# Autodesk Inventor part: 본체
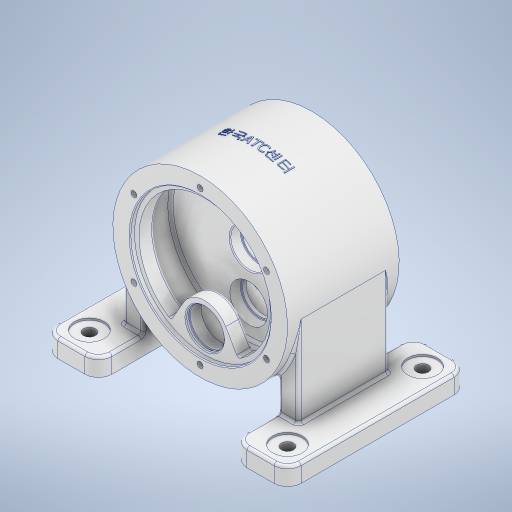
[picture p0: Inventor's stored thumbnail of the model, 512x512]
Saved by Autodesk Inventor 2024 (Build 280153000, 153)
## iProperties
Created: 2025-12
Part Number: 본체
Material: 알루미늄 6061
Document SubType Name: Modeling
Designer: Eud07
Density: 2.7 g/cm^3
Appearance: 알루미늄 - 평지
Mass: 5626.86 g
Surface Area: 3057.42 cm^2
Volume: 2084.02 cm^3
Author: Eud07
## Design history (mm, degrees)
sketch "스케치1"
  geometry: L1 (-97, -62)-(97, -62); L2 (97, -62)-(97, 62); L3 (97, 62)-(-97, 62); L4 (-97, 62)-(-97, -62); L5 (-97, -62)-(97, 62); L6 (97, -62)-(-97, 62); L7 (0, 62)-(0, -62); L8 (78, 62)-(78, 57); L9 (78, 57)-(73, 57); L10 (73, 57)-(73, 40); L11 (73, 40)-(87, 40); L12 (87, 40)-(87, 8); L13 (87, 8)-(0, 8); L14 (97, 0)-(0, 0); L15 (78, -62)-(78, -57); L16 (78, -57)-(73, -57); L17 (73, -57)-(73, -40); L18 (73, -40)-(87, -40); L19 (87, -40)-(87, -8); L20 (87, -8)-(0, -8); 2 further points
  constraints: 40 end point, 7 symmetric about line, 6 perpendicular, 5 midpoint, 2 horizontal, 2 parallel, 2 point on line, 1 vertical
  dimensions: "d0" = 124 distance of L1.end L2.end; "d1" = 97 distance between parallel lines of L7 L2; "d2" = 22 distance between parallel lines of L11 L3; "d3" = 5 distance of L8.start L8.end; "d4" = 32 distance of L11.end L12.end; "d5" = 78 distance between parallel lines of L7 L8; "d6" = 73 distance between parallel lines of L7 L10; "d7" = 87 distance between parallel lines of L7 L12
revolve "회전1" sketch "스케치1" stored, may be unused: angle "d8" = 90 deg
feature "면 삭제1"
sketch "스케치2" dims "d10" = 54
  geometry: L1 (-23.383, -39)-(-61.06, -104.259); L2 (0, 0)-(0, -116.93); L3 (23.383, -39)-(61.06, -104.259); C1 r 73 at (0, 0); 5 further points
  constraints: 6 end point, 2 symmetric about line, 1 centre point, 1 coincident, 1 vertical, 1 vertical alignment, 4 other
  dimensions: "d9" = 146 diameter of C1; "d11" = 52.5 distance of point (0, -52.5) point (0, 0); "d12" = 30 deg angle of L2 L1
extrude "돌출1" cut sketch "스케치2" distance "d13" = 17; taper "d14" = 0 deg
sketch "스케치3"
  geometry: C1 r 21 at (0, 0); C2 r 21 at (0, -52.5); C3 r 19 at (0, 0); C4 r 19 at (0, -52.5); A1 r 27 centre (0, -52.5) between (23.383, -39) and (-23.383, -39) reference; 1 further point
  constraints: 4 centre point, 3 coincident, 1 concentric
  dimensions: "d15" = 42 diameter of C1; "d16" = 42 diameter of C2; "d17" = 38 diameter of C3; "d18" = 38 diameter of C4
extrude "돌출2" cut sketch "스케치3" distance "d19" = 66; taper "d20" = 0 deg
extrude "돌출3" cut sketch "스케치3" extent not by distance; stored distance "d21" = 0; taper "d22" = 0 deg
sketch "스케치4"
  geometry: L1 (-52.5, 76.931)-(-52.5, 27.612); L2 (-87, 8)-(87, 8) reference; L3 (-73.5, 57)-(-31.5, 57) reference; L4 (-31.5, 57)-(-31.5, 40) reference; L5 (-31.5, 53.95)-(-30.25, 53.95); L6 (-30.25, 53.95)-(-30.25, 52); L7 (-30.25, 52)-(-31.5, 52); L8 (-31.5, 52)-(-31.5, 53.95); L9 (-39, 40)-(-25.5, 40) reference; 2 further points
  constraints: 10 end point, 2 parallel, 2 perpendicular, 1 horizontal, 1 point on line
  dimensions: "d23" = 21 distance from line of L3.end L1; "d24" = 1.95 distance of L5.end L6.end; "d25" = 12 distance between parallel lines of L9 L7; "d26" = 22.25 distance between parallel lines of L1 L6
revolve "회전2" sketch "스케치4" stored, may be unused: angle "d27" = 90 deg
node "작업 평면1"
sketch "스케치6"
  geometry: L1 (135, -100)-(75, -100); L2 (75, -100)-(75, 100); L3 (75, 100)-(135, 100); L4 (135, 100)-(135, -100); L5 (135, -100)-(75, 100); L6 (75, -100)-(135, 100); L7 (75, -50)-(97, -50); L8 (97, -50)-(97, 50); L9 (97, 50)-(75, 50); L10 (75, 50)-(75, -50); 3 further points
  constraints: 20 end point, 4 parallel, 2 horizontal, 2 midpoint, 2 perpendicular, 1 horizontal alignment, 1 point on line
  dimensions: "d29" = 60 distance of L2.end L3.end; "d30" = 75 distance from line of point (0, 0) L2; "d31" = 200 distance of L3.end L1.start; "d32" = 22 distance of L8.end L9.end; "d33" = 100 distance of L7.end L8.end; "d34" = 50 distance from line of point (0, 0) L7
extrude "돌출4" join sketch "스케치6" distance "d35" = 20; taper "d36" = 0 deg
extrude "돌출5" join sketch "스케치6" stored distance "d37" = 20; taper "d38" = 0 deg
fillet "모깎기1" dims "d39" = 15
sketch "스케치7"
  geometry: L1 (-135, 85)-(-135, -85) reference; L2 (73, -57)-(-73, -57) reference; 6 further points
  constraints: 2 midpoint
  dimensions: "d40" = 75 vertical distance of point (-135, 0) point (-110, 75); "d41" = 110 horizontal distance of point (0, -57) point (-110, 75)
hole "구멍1" sketch "스케치7" at (-110, 75) diameter "d42" = 13.5; stored, may be unused: countersink angle "d46" = 90 deg, drill point angle "d48" = 118 deg; dims "d43" = 6, "d44" = 33, "d45" = 2, "d47" = 8
sketch "스케치8"
  geometry: L1 (-75, -120)-(-75, -100) reference; L2 (-75, -112)-(-36.6, -89.83); L3 (-75, -100)-(-75, -61.514) reference; L4 (-75, -120)-(-90, -120) reference; A1 r 97 centre (0, 0) between (-36.6, -89.83) and (-75, -61.514) reference; 2 further points
  constraints: 2 end point, 1 coincident, 1 point on circle, 1 point on line
  dimensions: "d49" = 60 deg angle of L2 L3; "d50" = 8 distance from line of L4 point (-75, -112)
feature "리브1" sketch "스케치8" dims "d51" = 1, "d52" = 12, "d53" = 0, "d54" = 0, "d55" = 1, "d56" = 1
sketch "스케치9"
  geometry: 2 further points
  constraints: 1 vertical alignment
  dimensions: "d57" = 85 distance of point (0, 0) point (0, 85)
hole "구멍2" sketch "스케치9" at (0, 85) diameter "d58" = 6.647; stored, may be unused: countersink angle "d62" = 90 deg, drill point angle "d64" = 118 deg; dims "d59" = 16, "d60" = 33, "d61" = 2, "d63" = 18
node "작업 평면2"
sketch "스케치10"
  geometry: 2 further points
  constraints: 1 coincident, 1 other
feature "엠보싱1" sketch "스케치10" dims "d69" = 0.5, "d70" = 0
fillet "모깎기2" dims "d71" = 0.6
fillet "모깎기3" dims "d72" = 3
fillet "모깎기4" dims "d73" = 3
fillet "모깎기5" dims "d74" = 3
chamfer "모따기1" distance "d75" = 1; stored, may be unused: second distance "d76" = 2, angle "d77" = 45 deg
fillet "모깎기6" dims "d78" = 3
fillet "모깎기7" dims "d79" = 3
chamfer "모따기2" distance "d80" = 1; stored, may be unused: second distance "d81" = 2, angle "d82" = 45 deg
chamfer "모따기3" distance "d83" = 1; stored, may be unused: second distance "d84" = 2, angle "d85" = 45 deg
node "솔리드1"
mirror "미러1"
mirror "미러2"
pattern_circular "원형 패턴1" dims angle "d66" = 360 deg
mirror "미러3"
feature "A9D066F2-1C7D-4E18-AEED-F7BC21143FA4" dims "d58" = 6.647, "d59" = 16, "d60" = 33, "d61" = 2, "d62" = 90 deg, "d63" = 18, "d64" = 118 deg
other parameters: "d68" = 160.25
